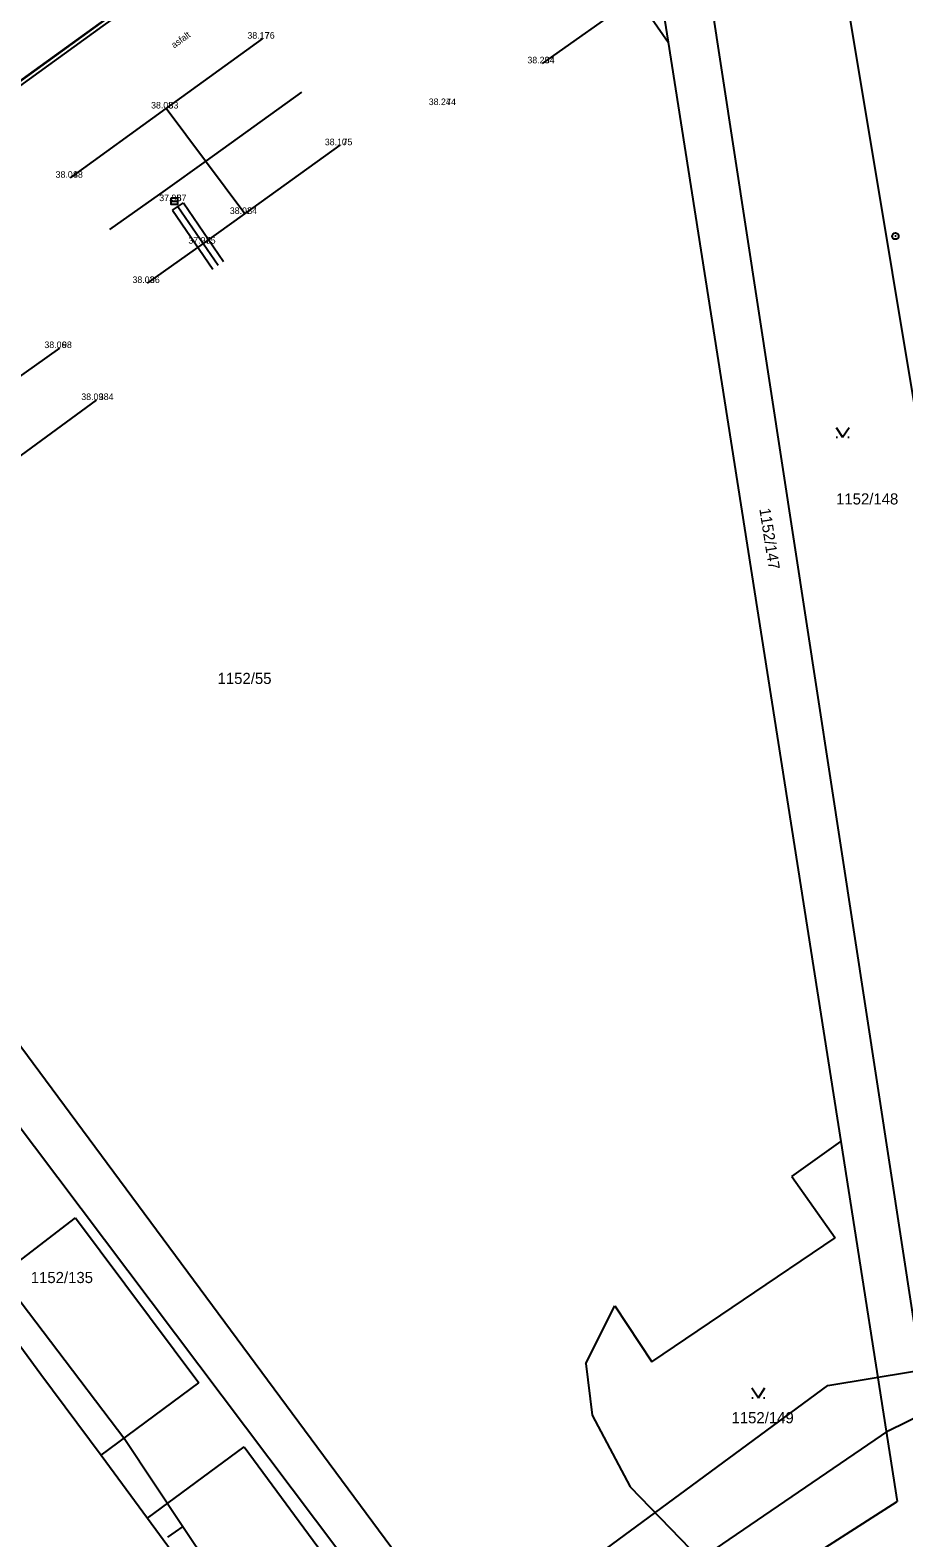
# Model space of a CAD drawing. Extents: x -609709 to -609357, y -1051535 to -1051131.
# Drawn here: x -609530.2 to -609496.9, y -1051388.6 to -1051331.1 of the extents above; entities that cross this region are included whole.
import ezdxf

# ---------------------------------------------------------------- set-up
doc = ezdxf.new("R2010")
doc.units = 0
for name, color, linetype in [('Vrstva 1', 7, 'Continuous'), ('Vrstva 10', 7, 'Continuous'), ('Vrstva 12', 7, 'Continuous'), ('Vrstva 2', 7, 'Continuous'), ('Vrstva 3', 7, 'Continuous'), ('Vrstva 4', 7, 'Continuous'), ('Vrstva 5', 7, 'Continuous')]:
    doc.layers.add(name, color=color, linetype=linetype)

msp = doc.modelspace()

# ---------------------------------------------------------------- linework, layer by layer
at = {"layer": 'Vrstva 1'}
for p, q in [((-609521.35, -1051331.46), (-609521.35, -1051331.46)), ((-609510.68, -1051332.4), (-609510.68, -1051332.4)), ((-609514.44, -1051333.99), (-609514.44, -1051333.99)), ((-609525.02, -1051334.12), (-609525.02, -1051334.12)), ((-609518.39, -1051335.52), (-609518.39, -1051335.52)), ((-609528.66, -1051336.76), (-609528.66, -1051336.76)), ((-609524.71, -1051337.65), (-609524.71, -1051337.65)), ((-609522.02, -1051338.14), (-609522.02, -1051338.14)), ((-609523.6, -1051339.27), (-609523.6, -1051339.27)), ((-609525.73, -1051340.77), (-609525.73, -1051340.77)), ((-609529.08, -1051343.25), (-609529.08, -1051343.25)), ((-609527.68, -1051345.23), (-609527.68, -1051345.23))]:
    msp.add_line(p, q, dxfattribs=at)
at = {"layer": 'Vrstva 10'}
for p, q in [((-609581.79, -1051300.71), (-609506.66, -1051402.14)), ((-609541.54, -1051340.98), (-609507.4, -1051316.31)), ((-609505.79, -1051320.08), (-609495.64, -1051386.18)), ((-609507.52, -1051321.23), (-609505.89, -1051331.59)), ((-609500.39, -1051322.14), (-609491.56, -1051375.22)), ((-609511.08, -1051324.1), (-609505.89, -1051331.59)), ((-609505.89, -1051331.59), (-609499.31, -1051373.48)), ((-609499.49, -1051346.275), (-609499.24, -1051346.65)), ((-609499.49, -1051346.65), (-609499.44, -1051346.65)), ((-609499.24, -1051346.65), (-609498.99, -1051346.275)), ((-609499.04, -1051346.65), (-609498.99, -1051346.65)), ((-609501.18, -1051374.82), (-609499.31, -1051373.48)), ((-609499.31, -1051373.48), (-609497.16, -1051387.2)), ((-609501.18, -1051374.82), (-609499.52, -1051377.15)), ((-609532.12, -1051379.19), (-609528.48, -1051376.39)), ((-609528.48, -1051376.39), (-609523.78, -1051382.68)), ((-609506.51, -1051381.88), (-609499.52, -1051377.15)), ((-609532.12, -1051379.19), (-609529.79, -1051382.35)), ((-609509.03, -1051381.95), (-609507.92, -1051379.74)), ((-609507.92, -1051379.74), (-609506.51, -1051381.88)), ((-609529.79, -1051382.35), (-609527.5, -1051385.44)), ((-609509.03, -1051381.95), (-609508.78, -1051383.91)), ((-609527.5, -1051385.44), (-609523.78, -1051382.68)), ((-609502.7, -1051382.875), (-609502.45, -1051383.25)), ((-609502.45, -1051383.25), (-609502.2, -1051382.875)), ((-609502.7, -1051383.25), (-609502.65, -1051383.25)), ((-609502.25, -1051383.25), (-609502.2, -1051383.25)), ((-609508.78, -1051383.91), (-609507.34, -1051386.64)), ((-609525.73, -1051387.84), (-609522.05, -1051385.12)), ((-609522.05, -1051385.12), (-609509.14, -1051402.6)), ((-609527.5, -1051385.44), (-609525.73, -1051387.84)), ((-609507.34, -1051386.64), (-609505.05, -1051389)), ((-609502.29, -1051390.48), (-609497.16, -1051387.2)), ((-609525.73, -1051387.84), (-609519.01, -1051396.92))]:
    msp.add_line(p, q, dxfattribs=at)
for radius in [0.125, 0.0025]:
    msp.add_circle((-609497.23, -1051338.98), radius, dxfattribs=at)
at = {"layer": 'Vrstva 12'}
for points in [[(-609615.546, -1051325.052), (-609614.108, -1051326.974), (-609589.099, -1051308.266), (-609582.815, -1051303.565), (-609514.844, -1051393.856), (-609499.807, -1051382.785), (-609467.693, -1051377.467)], [(-609513.99, -1051396.17), (-609509.03, -1051392.84), (-609504.6, -1051389.36), (-609497.48, -1051384.5), (-609490.61, -1051381.13), (-609487.01, -1051379.99), (-609478.64, -1051378.48), (-609473.03, -1051377.23), (-609472.37, -1051375.01), (-609472.654, -1051372.8)], [(-609535.11, -1051373.63), (-609526.59, -1051384.83), (-609524.39, -1051388.15), (-609524.969, -1051388.565)], [(-609524.39, -1051388.15), (-609523.38, -1051389.65), (-609518.63, -1051395.89), (-609516.34, -1051397.91), (-609520.11, -1051398.25), (-609520.283, -1051397.9)]]:
    msp.add_lwpolyline(points, dxfattribs=at)
at = {"layer": 'Vrstva 4'}
for p, q in [((-609524.775, -1051337.998), (-609524.362, -1051337.715)), ((-609524.775, -1051337.998), (-609523.239, -1051340.239)), ((-609524.362, -1051337.715), (-609522.831, -1051339.95))]:
    msp.add_line(p, q, dxfattribs=at)
for points in [[(-609567.69, -1051305.73), (-609565.19, -1051309.21), (-609561.45, -1051314.29), (-609556.48, -1051321.05), (-609552.89, -1051325.9), (-609549.26, -1051330.78), (-609545.88, -1051335.35), (-609541.56, -1051341.2), (-609537.96, -1051338.59), (-609534.58, -1051336.17), (-609530.96, -1051333.54), (-609527.42, -1051330.97), (-609523.72, -1051328.34), (-609521.12, -1051326.49), (-609517.15, -1051323.61), (-609513.51, -1051320.93), (-609509.43, -1051317.99)], [(-609531.042, -1051333.427), (-609527.502, -1051330.856), (-609523.801, -1051328.226)], [(-609510.68, -1051332.4), (-609507.186, -1051329.926)], [(-609528.66, -1051336.76), (-609525.02, -1051334.12), (-609521.35, -1051331.46)], [(-609527.169, -1051338.726), (-609525.047, -1051337.231), (-609523.479, -1051336.11), (-609519.853, -1051333.493)], [(-609522.02, -1051338.14), (-609525.02, -1051334.12)], [(-609525.73, -1051340.77), (-609523.6, -1051339.27), (-609522.02, -1051338.14), (-609518.39, -1051335.52)], [(-609524.569, -1051337.856), (-609523.035, -1051340.095)], [(-609529.08, -1051343.25), (-609532.78, -1051345.87), (-609536.39, -1051348.52)], [(-609534.94, -1051350.52), (-609531.3, -1051347.89), (-609527.68, -1051345.23)]]:
    msp.add_lwpolyline(points, dxfattribs=at)
at = {"layer": 'Vrstva 5'}
msp.add_line((-609524.835, -1051337.65), (-609524.585, -1051337.65), dxfattribs=at)
msp.add_lwpolyline([(-609524.835, -1051337.525), (-609524.585, -1051337.525), (-609524.585, -1051337.775), (-609524.835, -1051337.775)], close=True, dxfattribs=at)

# ---------------------------------------------------------------- texts
at = {"layer": 'Vrstva 10'}
for s, p in [('1152/148', (-609499.49, -1051349.21)), ('1152/55', (-609523.06, -1051356.05)), ('1152/135', (-609530.18, -1051378.88)), ('1152/149', (-609503.475, -1051384.222))]:
    msp.add_text(s, height=0.425, dxfattribs=at).set_placement(p)
msp.add_text('1152/147', height=0.425, rotation=279, dxfattribs=at).set_placement((-609502.418, -1051349.376))
at = {"layer": 'Vrstva 2'}
for s, p in [(' 76', (-609521.35, -1051331.46)), (' 34', (-609510.68, -1051332.4)), (' 83', (-609525.02, -1051334.12)), (' 74', (-609514.44, -1051333.99)), (' 75', (-609518.39, -1051335.52)), (' 88', (-609528.66, -1051336.76)), (' 87', (-609524.71, -1051337.65)), (' 84', (-609522.02, -1051338.14)), (' 85', (-609523.6, -1051339.27)), (' 86', (-609525.73, -1051340.77)), (' 98', (-609529.08, -1051343.25)), (' 384', (-609527.68, -1051345.23))]:
    msp.add_text(s, height=0.25, dxfattribs=at).set_placement(p)
at = {"layer": 'Vrstva 3'}
for s, p in [('38.17', (-609521.923, -1051331.46)), ('38.29', (-609511.253, -1051332.4)), ('38.08', (-609525.593, -1051334.12)), ('38.24', (-609515.013, -1051333.99)), ('38.10', (-609518.973, -1051335.52)), ('38.04', (-609529.233, -1051336.76)), ('37.95', (-609525.283, -1051337.65)), ('38.02', (-609522.593, -1051338.14)), ('37.97', (-609524.173, -1051339.27)), ('38.03', (-609526.303, -1051340.77)), ('38.06', (-609529.659, -1051343.25)), ('38.09', (-609528.253, -1051345.23))]:
    msp.add_text(s, height=0.25, dxfattribs=at).set_placement(p)
at = {"layer": 'Vrstva 4'}
msp.add_text('asfalt', height=0.25, rotation=35.95243, dxfattribs=at).set_placement((-609524.716, -1051331.838))

doc.saveas('drawing.dxf')
